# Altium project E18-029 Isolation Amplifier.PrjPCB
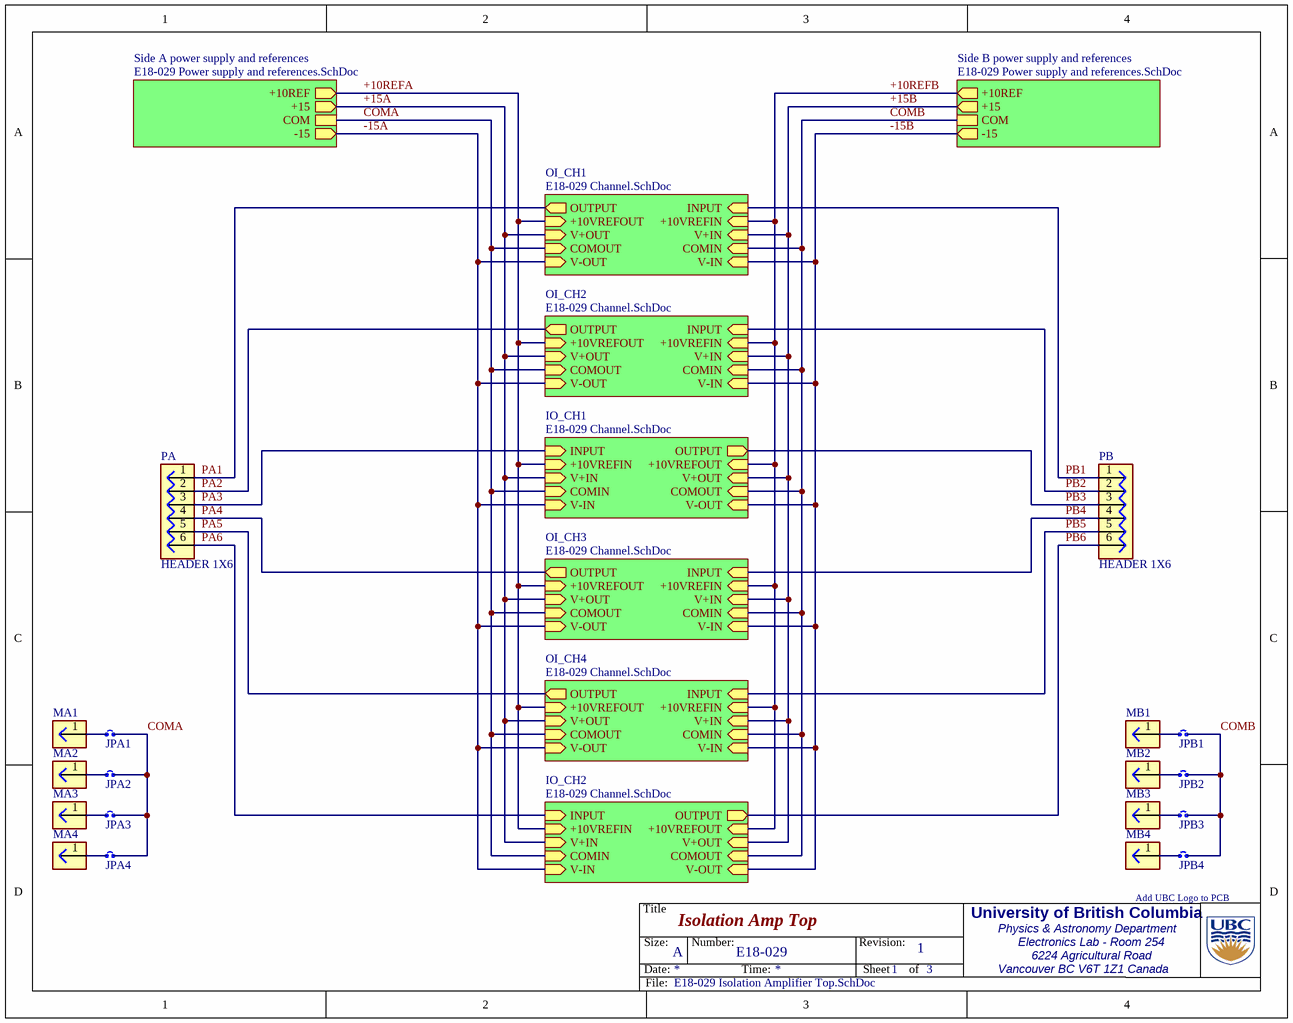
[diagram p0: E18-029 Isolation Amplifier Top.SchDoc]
3 sheets, 359 parts. Net scope: hierarchical (ports join the sheet entries above them; power ports are global).
Board file: E18-029 Isolation Amplifier.PcbDoc
Sheets:
  E18-029 Isolation Amplifier Top.SchDoc
    Side B power supply and references = E18-029 Power supply and references.SchDoc
    Side A power supply and references = E18-029 Power supply and references.SchDoc
    IO_CH1 = E18-029 Channel.SchDoc
    IO_CH2 = E18-029 Channel.SchDoc
    OI_CH1 = E18-029 Channel.SchDoc
    OI_CH2 = E18-029 Channel.SchDoc
    OI_CH3 = E18-029 Channel.SchDoc
    OI_CH4 = E18-029 Channel.SchDoc

## Sheet E18-029 Isolation Amplifier Top.SchDoc: Isolation Amp Top
size A; Author: MC; DrawnBy: M. Carlson; Organization: University of British Columbia; Address1: Physics & Astronomy Department; Address2: Electronics Lab - Room 254; Address3: 6224 Agricultural Road; Address4: Vancouver BC V6T 1Z1 Canada; DocumentNumber: E18-029; Revision: 1; SheetNumber: 1; SheetTotal: 3

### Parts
JPA1  JMPR  [Jumper 1210]  (value not drawn)
JPA2  JMPR  [Jumper 1210]  (value not drawn)
JPA3  JMPR  [Jumper 1210]  (value not drawn)
JPA4  JMPR  [Jumper 1210]  (value not drawn)
JPB1  JMPR  [Jumper 1210]  (value not drawn)
JPB2  JMPR  [Jumper 1210]  (value not drawn)
JPB3  JMPR  [Jumper 1210]  (value not drawn)
JPB4  JMPR  [Jumper 1210]  (value not drawn)
Logo?  Use UBC Logo  [UBC Logo]  (value not drawn)  (no BOM)
MA1  Pad  [Mtg_Hole_M4 no silk]  (value not drawn)
MA2  Pad  [Mtg_Hole_M4 no silk]  (value not drawn)
MA3  Pad  [Mtg_Hole_M4 no silk]  (value not drawn)
MA4  Pad  [Mtg_Hole_M4 no silk]  (value not drawn)
MB1  Pad  [Mtg_Hole_M4 no silk]  (value not drawn)
MB2  Pad  [Mtg_Hole_M4 no silk]  (value not drawn)
MB3  Pad  [Mtg_Hole_M4 no silk]  (value not drawn)
MB4  Pad  [Mtg_Hole_M4 no silk]  (value not drawn)
PA  HEADER 1X6  [HDR1X6 SMD]
PB  HEADER 1X6  [HDR1X6 SMD]

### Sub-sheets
IO_CH1 = E18-029 Channel.SchDoc: +10VREFIN (in), INPUT (in), +10VREFOUT (in), OUTPUT (out), V+IN (in), V-IN (in), COMIN (in), V+OUT (in), V-OUT (in), COMOUT (in)
IO_CH2 = E18-029 Channel.SchDoc: +10VREFIN (in), INPUT (in), +10VREFOUT (in), OUTPUT (out), V+IN (in), V-IN (in), COMIN (in), V+OUT (in), V-OUT (in), COMOUT (in)
OI_CH1 = E18-029 Channel.SchDoc: +10VREFIN (in), INPUT (in), +10VREFOUT (in), OUTPUT (out), V+IN (in), V-IN (in), COMIN (in), V+OUT (in), V-OUT (in), COMOUT (in)
OI_CH2 = E18-029 Channel.SchDoc: +10VREFIN (in), INPUT (in), +10VREFOUT (in), OUTPUT (out), V+IN (in), V-IN (in), COMIN (in), V+OUT (in), V-OUT (in), COMOUT (in)
OI_CH3 = E18-029 Channel.SchDoc: +10VREFIN (in), INPUT (in), +10VREFOUT (in), OUTPUT (out), V+IN (in), V-IN (in), COMIN (in), V+OUT (in), V-OUT (in), COMOUT (in)
OI_CH4 = E18-029 Channel.SchDoc: +10VREFIN (in), INPUT (in), +10VREFOUT (in), OUTPUT (out), V+IN (in), V-IN (in), COMIN (in), V+OUT (in), V-OUT (in), COMOUT (in)
Side A power supply and references = E18-029 Power supply and references.SchDoc: +15 (out), COM, -15 (out), +10REF (out)
Side B power supply and references = E18-029 Power supply and references.SchDoc: +15 (out), COM, -15 (out), +10REF (out)

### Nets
+15A: sheet Side B power supply and references/+15, sheet Side A power supply and references/+15, sheet IO_CH1/V+IN, sheet IO_CH1/V+OUT, sheet IO_CH2/V+IN, sheet IO_CH2/V+OUT, sheet OI_CH1/V+IN, sheet OI_CH1/V+OUT, sheet OI_CH2/V+IN, sheet OI_CH2/V+OUT, sheet OI_CH3/V+IN, sheet OI_CH3/V+OUT, sheet OI_CH4/V+IN, sheet OI_CH4/V+OUT  [also labelled +15B]
-15A: sheet Side B power supply and references/-15, sheet Side A power supply and references/-15, sheet IO_CH1/V-IN, sheet IO_CH1/V-OUT, sheet IO_CH2/V-IN, sheet IO_CH2/V-OUT, sheet OI_CH1/V-IN, sheet OI_CH1/V-OUT, sheet OI_CH2/V-IN, sheet OI_CH2/V-OUT, sheet OI_CH3/V-IN, sheet OI_CH3/V-OUT, sheet OI_CH4/V-IN, sheet OI_CH4/V-OUT  [also labelled -15B]
COMA: JPA1.2 JPA2.2 JPA3.2 JPA4.2 JPB1.2 JPB2.2 JPB3.2 JPB4.2 ; sheet Side B power supply and references/COM, sheet Side A power supply and references/COM, sheet IO_CH1/COMIN, sheet IO_CH1/COMOUT, sheet IO_CH2/COMIN, sheet IO_CH2/COMOUT, sheet OI_CH1/COMIN, sheet OI_CH1/COMOUT, sheet OI_CH2/COMIN, sheet OI_CH2/COMOUT, sheet OI_CH3/COMIN, sheet OI_CH3/COMOUT, sheet OI_CH4/COMIN, sheet OI_CH4/COMOUT  [also labelled COMB]
+10REFA: sheet Side A power supply and references/+10REF, sheet IO_CH1/+10VREFIN, sheet IO_CH2/+10VREFIN, sheet OI_CH1/+10VREFOUT, sheet OI_CH2/+10VREFOUT, sheet OI_CH3/+10VREFOUT, sheet OI_CH4/+10VREFOUT
+10REFB: sheet Side B power supply and references/+10REF, sheet IO_CH1/+10VREFOUT, sheet IO_CH2/+10VREFOUT, sheet OI_CH1/+10VREFIN, sheet OI_CH2/+10VREFIN, sheet OI_CH3/+10VREFIN, sheet OI_CH4/+10VREFIN
PA1: PA.1 ; sheet OI_CH1/OUTPUT
PA2: PA.2 ; sheet OI_CH2/OUTPUT
PA3: PA.3 ; sheet IO_CH1/INPUT
PA4: PA.4 ; sheet OI_CH3/OUTPUT
PA5: PA.5 ; sheet OI_CH4/OUTPUT
PA6: PA.6 ; sheet IO_CH2/INPUT
PB1: PB.1 ; sheet OI_CH1/INPUT
PB2: PB.2 ; sheet OI_CH2/INPUT
PB3: PB.3 ; sheet IO_CH1/OUTPUT
PB4: PB.4 ; sheet OI_CH3/INPUT
PB5: PB.5 ; sheet OI_CH4/INPUT
PB6: PB.6 ; sheet IO_CH2/OUTPUT
NetJPA1_1: JPA1.1 MA1.1
NetJPA2_1: JPA2.1 MA2.1
NetJPA3_1: JPA3.1 MA3.1
NetJPA4_1: JPA4.1 MA4.1
NetJPB1_1: JPB1.1 MB1.1
NetJPB2_1: JPB2.1 MB2.1
NetJPB3_1: JPB3.1 MB3.1
NetJPB4_1: JPB4.1 MB4.1

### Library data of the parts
JPA1-JPA4 JPB1-JPB4 = Jumper2P_SMD: 2 Pin Jumper Solder Pads; Manufacturer: Generic Components; Class: Passive
Logo? = Directive: Add UBC Logo to PCB: UBC Logo
MA1-MA4 MB1-MB4 = Mounting Pad: Manufacturer: AMP; Part No.: PAD_HV
PA PB = HEADER 1X6: 0.1" Spacing 1x6 Header; Manufacturer: AMP

## Sheet E18-029 Power supply and references.SchDoc: Power Supply and Reference
size A; DrawnBy: M. Carlson; Organization: University of British Columbia; Address1: Physics & Astronomy Department; Address2: Electronics Lab - Room 254; Address3: 6224 Agricultural Road; Address4: Vancouver BC V6T 1Z1 Canada; DocumentNumber: E18-029; Revision: 1; SheetNumber: 2; SheetTotal: 3
Used 2 times, as channels Side B power supply and references, Side A power supply and references. Parts and nets are listed once, with the designators drawn on the sheet.
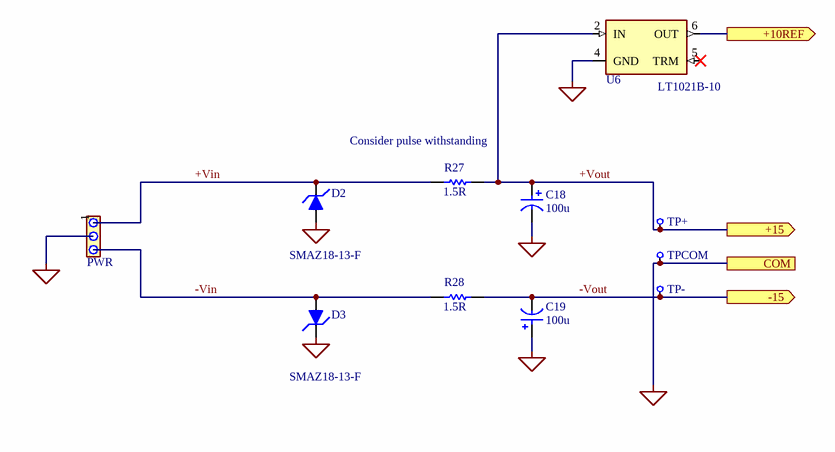
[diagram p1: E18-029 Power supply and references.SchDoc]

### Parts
C18  value 100u  [CC7343]  (hidden comment: CAP TANT POLY 100UF 25V 2917)
C19  value 100u  [CC7343]  (hidden comment: CAP TANT POLY 100UF 25V 2917)
D2  SMAZ18-13-F  [SMAJ]
D3  SMAZ18-13-F  [SMAJ]
PWR  JMPR  [HDR1X3 SMD]  (value not drawn)
R27  1.5R  [R1206]
R28  1.5R  [R1206]
TP+  Vero Eyelet Test Point  [TEST PT SMD]  (value not drawn)
TP-  Vero Eyelet Test Point  [TEST PT SMD]  (value not drawn)
TPCOM  Vero Eyelet Test Point  [PAD-110-52]  (value not drawn)
U6  LT1021B-10  [SO-G8]

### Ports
+10REF (out), +15 (out), -15 (out), COM

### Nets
GND: C18.2 C19.1 D2.1(A) D3.2(K) PWR.2 TPCOM.1 U6.4(GND) ; port COM
+10REF: U6.6(OUT) ; port +10REF
+Vin: D2.2(K) PWR.1 R27.2
+Vout: C18.1 R27.1 TP+.1 U6.2(IN) ; port +15
-Vin: D3.1(A) PWR.3 R28.2
-Vout: C19.2 R28.1 TP-.1 ; port -15

Not connected (* = marked no-connect by the designer): U6 5(TRM)*

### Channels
Side B power supply and references: designators end in _Side_B_power_supply_and_references; ports +10REF=+10REFB +15=+15A -15=-15A COM=COMA
Side A power supply and references: designators end in _Side_A_power_supply_and_references; ports +10REF=+10REFA +15=+15A -15=-15A COM=COMA

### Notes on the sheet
- Consider pulse withstanding

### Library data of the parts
C18 C19 = Cap Tant 100uF 10V: Manufacturer: AVX; Part Number: TCJE107M025R0080; Class: Passive; SubClass: Capacitor; Type: SMD; Scuba2 No.: 000523 CAP
D2 D3 = SMAZ18-13-F: Zener, 18V 1W SMAJ; Part Number: SMAZ15-13-F; Manufacturer: MCC; Class: Discrete; Subclass: Zener Diode; Type: SMT
PWR = Jumper3p: 3 Pin Jumper Header; Manufacturer: Generic Components; Class: Passive
R27 R28 = Res1: Resistor
TP+ TP- TPCOM = TP- Eyelet Terminal: Eyelet Test Point (white); Part Number: 20-313143A; Class: Passive
U6 = LT1021B-10: 2ppm/°C, Low-Noise, +10V Voltage Reference; Manufacturer: Maxim; Part Number: MAX6325CSA; Class: Power Management

## Sheet E18-029 Channel.SchDoc: Analog Channel
size A; Author: Mark Carlson; Organization: University of British Columbia; Address1: Physics & Astronomy Department; Address2: Electronics Lab - Room 254; Address3: 6224 Agricultural Road; Address4: Vancouver BC V6T 1Z1 Canada; DocumentNumber: E18-029; Revision: 1; SheetNumber: 3; SheetTotal: 3
Used 6 times, as channels IO_CH1, IO_CH2, OI_CH1, OI_CH2, OI_CH3, OI_CH4. Parts and nets are listed once, with the designators drawn on the sheet.
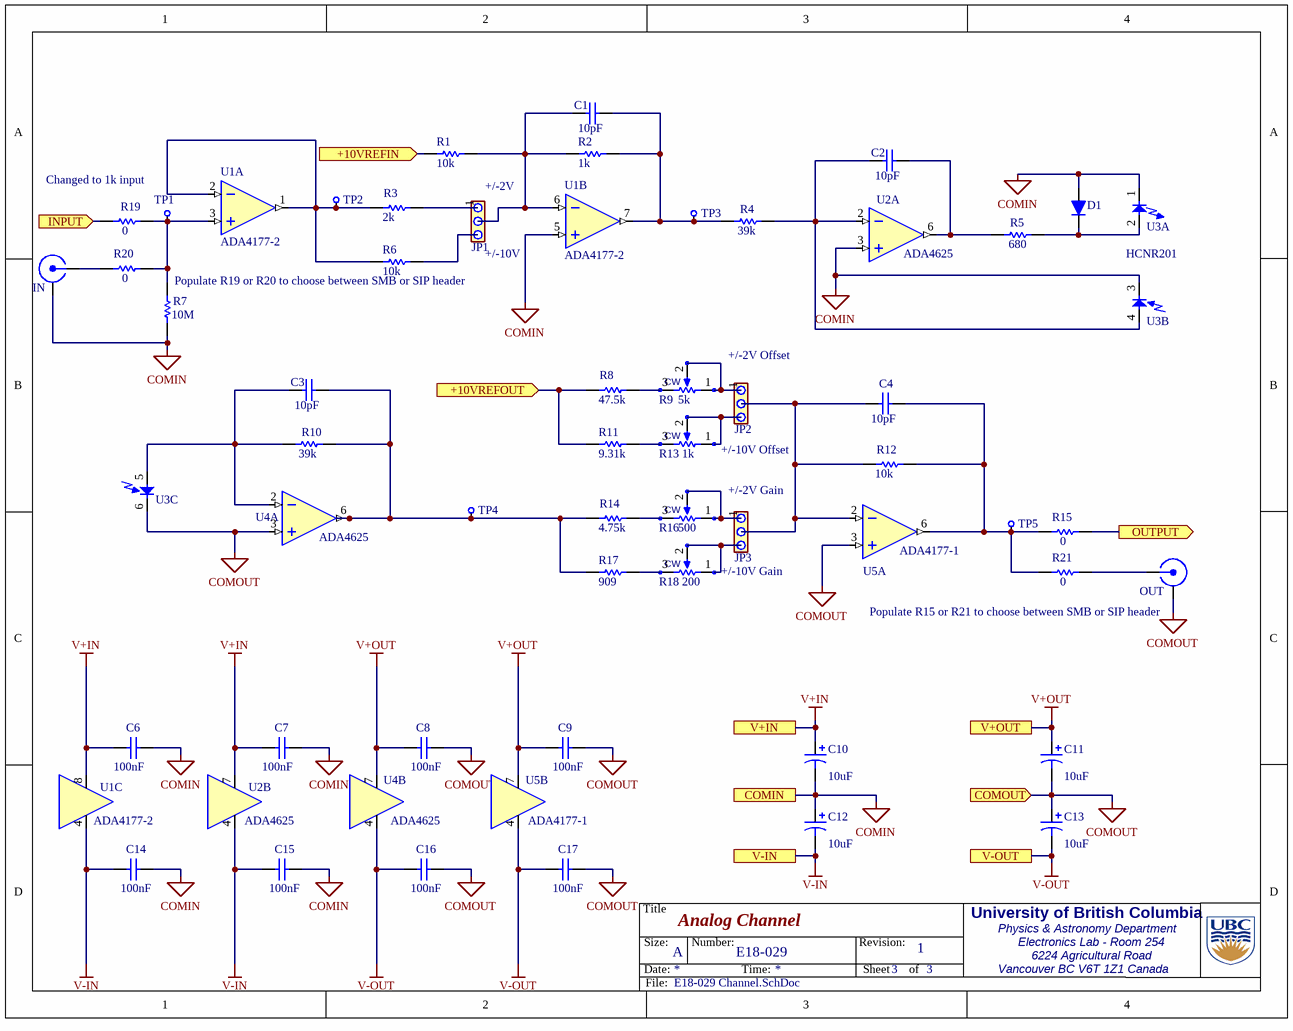
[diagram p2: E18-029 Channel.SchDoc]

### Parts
C1  10pF  [6-0805_M]
C2  10pF  [6-0805_M]
C3  10pF  [6-0805_M]
C4  10pF  [6-0805_M]
C6  100nF  [6-0805_M]
C7  100nF  [6-0805_M]
C8  100nF  [6-0805_M]
C9  100nF  [6-0805_M]
C10  value 10uF  [CC3216]  (hidden comment: Tant Poly 10uF)
C11  value 10uF  [CC3216]  (hidden comment: Tant Poly 10uF)
C12  value 10uF  [CC3216]  (hidden comment: Tant Poly 10uF)
C13  value 10uF  [CC3216]  (hidden comment: Tant Poly 10uF)
C14  100nF  [6-0805_M]
C15  100nF  [6-0805_M]
C16  100nF  [6-0805_M]
C17  100nF  [6-0805_M]
D1  1N4148W  [SOD-123]  (value not drawn)
IN  SMB Male Vertical Mount  [SMB_Male_Vertical]  (value not drawn)
JP1  JMPR  [HDR1X3 SMD]  (value not drawn)
JP2  JMPR  [HDR1X3 SMD]  (value not drawn)
JP3  JMPR  [HDR1X3 SMD]  (value not drawn)
OUT  SMB Male Vertical Mount  [SMB_Male_Vertical]  (value not drawn)
R1  10k  [6-0805_M]
R2  1k  [6-0805_M]
R3  2k  [6-0805_M]
R4  39k  [R1206]
R5  680  [6-0805_M]
R6  10k  [6-0805_M]
R7  10M  [6-0805_M]
R8  47.5k  [6-0805_M]
R9  value 5k  End: CW  [POT SMD]  (hidden comment: RPot8)
R10  39k  [6-0805_M]
R11  9.31k  [6-0805_M]
R12  10k  [6-0805_M]
R13  value 1k  End: CW  [POT SMD]  (hidden comment: RPot8)
R14  4.75k  [6-0805_M]
R15  0  [6-0805_M]
R16  value 500  End: CW  [POT SMD]  (hidden comment: RPot8)
R17  909  [6-0805_M]
R18  value 200  End: CW  [POT SMD]  (hidden comment: RPot8)
R19  0  [6-0805_M]
R20  value 0  [6-0805_M]  (hidden comment: 2.2k)
R21  0  [6-0805_M]
TP1  Vero Eyelet Test Point  [TEST PT SMD]  (value not drawn)
TP2  Vero Eyelet Test Point  [TEST PT SMD]  (value not drawn)
TP3  Vero Eyelet Test Point  [TEST PT SMD]  (value not drawn)
TP4  Vero Eyelet Test Point  [TEST PT SMD]  (value not drawn)
TP5  Vero Eyelet Test Point  [TEST PT SMD]  (value not drawn)
U1  ADA4177-2  [SO-G8]  (parts A,B,C of 3)
U2  ADA4625  [SO-G8]  (parts A,B of 2)
U3  HCNR201  [DIP-8GW]  (parts A,B,C of 3)
U4  ADA4625  [SO-G8]  (parts A,B of 2)
U5  ADA4177-1  [SO-G8]  (parts A,B of 2)

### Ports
+10VREFIN (in), +10VREFOUT (in), COMIN, COMOUT (in), INPUT (in), OUTPUT (out), V+IN, V+OUT, V-IN, V-OUT

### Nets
COMIN: C6.1 C7.1 C10.2 C12.1 C14.1 C15.1 D1.1(A) IN.2 R7.1 U1.5(IN+2) U2.3(IN+) U3.1(LED_K) U3.3(PD1-K) ; port COMIN
COMOUT: C8.1 C9.1 C11.2 C13.1 C16.1 C17.1 OUT.2 U3.6(PD2-K) U4.3(IN+) U5.3(IN+) ; port COMOUT
V+IN: C6.2 C7.2 C10.1 U1.8(V+) U2.7(+Vs) ; port V+IN
V+OUT: C8.2 C9.2 C11.1 U4.7(+Vs) U5.7(+Vs) ; port V+OUT
V-IN: C12.2 C14.2 C15.2 U1.4(V-) U2.4(-Vs) ; port V-IN
V-OUT: C13.2 C16.2 C17.2 U4.4(-Vs) U5.4(-Vs) ; port V-OUT
+10VREFIN: R1.2 ; port +10VREFIN
+10VREFOUT: R8.2 R11.2 ; port +10VREFOUT
INPUT: R19.2 ; port INPUT
OUTPUT: R15.1 ; port OUTPUT
NetC1_1: C1.1 R2.1 R4.1 TP3.1 U1.7(OUT2)
NetC1_2: C1.2 JP1.2 R1.1 R2.2 U1.6(IN-2)
NetC2_1: C2.1 R5.1 U2.6(OUT)
NetC2_2: C2.2 R4.2 U2.2(IN-) U3.4(PD1-A)
NetC3_1: C3.1 R10.2 R14.2 R17.2 TP4.1 U4.6(OUT)
NetC3_2: C3.2 R10.1 U3.5(PD2-A) U4.2(IN-)
NetC4_1: C4.1 R12.1 R15.2 R21.2 TP5.1 U5.6(OUT)
NetC4_2: C4.2 JP2.2 JP3.2 R12.2 U5.2(IN-)
NetD1_2: D1.2(K) R5.2 U3.2(LED_A)
NetIN_1: IN.1 R20.2
NetJP1_1: JP1.1 R3.1
NetJP1_3: JP1.3 R6.1
NetJP2_1: JP2.1 R9.1 R9.2
NetJP2_3: JP2.3 R13.1 R13.2
NetJP3_1: JP3.1 R16.1 R16.2
NetJP3_3: JP3.3 R18.1 R18.2
NetOUT_1: OUT.1 R21.1
NetR3_2: R3.2 R6.2 TP2.1 U1.1(OUT1) U1.2(IN-1)
NetR7_2: R7.2 R19.1 R20.1 TP1.1 U1.3(IN+1)
NetR8_1: R8.1 R9.3
NetR11_1: R11.1 R13.3
NetR14_1: R14.1 R16.3
NetR17_1: R17.1 R18.3

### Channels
IO_CH1: designators end in _IO_CH1; ports +10VREFIN=+10REFA +10VREFOUT=+10REFB COMIN=COMA COMOUT=COMA INPUT=PA3 OUTPUT=PB3 V+IN=+15A V+OUT=+15A V-IN=-15A V-OUT=-15A
IO_CH2: designators end in _IO_CH2; ports +10VREFIN=+10REFA +10VREFOUT=+10REFB COMIN=COMA COMOUT=COMA INPUT=PA6 OUTPUT=PB6 V+IN=+15A V+OUT=+15A V-IN=-15A V-OUT=-15A
OI_CH1: designators end in _OI_CH1; ports +10VREFIN=+10REFB +10VREFOUT=+10REFA COMIN=COMA COMOUT=COMA INPUT=PB1 OUTPUT=PA1 V+IN=+15A V+OUT=+15A V-IN=-15A V-OUT=-15A
OI_CH2: designators end in _OI_CH2; ports +10VREFIN=+10REFB +10VREFOUT=+10REFA COMIN=COMA COMOUT=COMA INPUT=PB2 OUTPUT=PA2 V+IN=+15A V+OUT=+15A V-IN=-15A V-OUT=-15A
OI_CH3: designators end in _OI_CH3; ports +10VREFIN=+10REFB +10VREFOUT=+10REFA COMIN=COMA COMOUT=COMA INPUT=PB4 OUTPUT=PA4 V+IN=+15A V+OUT=+15A V-IN=-15A V-OUT=-15A
OI_CH4: designators end in _OI_CH4; ports +10VREFIN=+10REFB +10VREFOUT=+10REFA COMIN=COMA COMOUT=COMA INPUT=PB5 OUTPUT=PA5 V+IN=+15A V+OUT=+15A V-IN=-15A V-OUT=-15A

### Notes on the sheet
- Changed to 1k input
- (near JP1) +/-2V
- Populate R19 or R20 to choose between SMB or SIP header
- (near JP1) +/-10V
- +/-2V Offset
- +/-10V Offset
- +/-2V Gain
- +/-10V Gain
- Populate R15 or R21 to choose between SMB or SIP header

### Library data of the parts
C1-C4 C6-C9 C14-C17 = Cap: Capacitor
C10-C13 = Cap Pol3: CAP TANT POLY 10UF 25V 1206
D1 = 1N4148W: High Conductance Fast Diode; Manufacturer: Fairchild Semiconductor; Revised: 11-July-2000: SIM Model Added.; Class: Discrete; SubClass: Diode - Switching; Type: SMD
IN OUT = SMB_Male_Vertical: SMA Male Vertical Mount; Manufacturer: Amphenol; Class: Connector; Fitted: POP
JP1-JP3 = Jumper3p: as PWR on sheet E18-029 Power supply and references
R1-R8 R10-R12 R14 R15 R17 R19-R21 = Res1: Resistor
R9 R13 R16 R18 = RPot8: SMD POT; Manufacturer: Vishay; Part Number: TS63Y; Class: Passive; SubClass: Potentiometer
TP1-TP5 = TP- Eyelet Terminal: as TP+ on sheet E18-029 Power supply and references
U1 = ADA4177-2: OVP and EMI Protected, Precision, / Low Noise and Bias Current Dual Op Amp; Manufacturer: Analog Devices; Class: Analog; SubClass: Operational Amp
U2 = ADA4625: 36V, 18MHz, Low Noise, JFET Op Amp; Manufacturer: Analog Devices; Class: Amplifier; SubClass: Operational Amplifier
U3 = HCNR201: Analog Optocoupler; Manufacturer: Agilent; Class: Electrical Isolation; SubClass: Opto-coupler
U4 = ADA4625: 36V, 18MHz, Low Noise, JFET Op Amp; Manufacturer: Analog Devices; Part Number: AD548KR; Class: Amplifier; SubClass: Operational Amplifier
U5 = ADA4177-1: OVP and EMI Protected, Precision, / Low Noise and Bias Current Dual Op Amp; Manufacturer: Analog Devices; Class: Amplifier; SubClass: Operational Amplifier

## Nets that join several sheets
+15A: Side B power supply and references (C18_Side_B_power_supply_and_references.1 R27_Side_B_power_supply_and_references.1 TP+_Side_B_power_supply_and_references.1 U6_Side_B_power_supply_and_references.2), Side A power supply and references (C18_Side_A_power_supply_and_references.1 R27_Side_A_power_supply_and_references.1 TP+_Side_A_power_supply_and_references.1 U6_Side_A_power_supply_and_references.2), IO_CH1 (10 pins), IO_CH2 (10 pins), OI_CH1 (10 pins), OI_CH2 (10 pins), OI_CH3 (10 pins), OI_CH4 (10 pins)
-15A: Side B power supply and references (C19_Side_B_power_supply_and_references.2 R28_Side_B_power_supply_and_references.1 TP-_Side_B_power_supply_and_references.1), Side A power supply and references (C19_Side_A_power_supply_and_references.2 R28_Side_A_power_supply_and_references.1 TP-_Side_A_power_supply_and_references.1), IO_CH1 (10 pins), IO_CH2 (10 pins), OI_CH1 (10 pins), OI_CH2 (10 pins), OI_CH3 (10 pins), OI_CH4 (10 pins)
COMA: E18-029 Isolation Amplifier Top (8 pins), Side B power supply and references (7 pins), Side A power supply and references (7 pins), IO_CH1 (23 pins), IO_CH2 (23 pins), OI_CH1 (23 pins), OI_CH2 (23 pins), OI_CH3 (23 pins), OI_CH4 (23 pins)
+10REFA: Side A power supply and references (U6_Side_A_power_supply_and_references.6), IO_CH1 (R1_IO_CH1.2), IO_CH2 (R1_IO_CH2.2), OI_CH1 (R8_OI_CH1.2 R11_OI_CH1.2), OI_CH2 (R8_OI_CH2.2 R11_OI_CH2.2), OI_CH3 (R8_OI_CH3.2 R11_OI_CH3.2), OI_CH4 (R8_OI_CH4.2 R11_OI_CH4.2)
+10REFB: Side B power supply and references (U6_Side_B_power_supply_and_references.6), IO_CH1 (R8_IO_CH1.2 R11_IO_CH1.2), IO_CH2 (R8_IO_CH2.2 R11_IO_CH2.2), OI_CH1 (R1_OI_CH1.2), OI_CH2 (R1_OI_CH2.2), OI_CH3 (R1_OI_CH3.2), OI_CH4 (R1_OI_CH4.2)
PA1: E18-029 Isolation Amplifier Top (PA.1), OI_CH1 (R15_OI_CH1.1)
PA2: E18-029 Isolation Amplifier Top (PA.2), OI_CH2 (R15_OI_CH2.1)
PA3: E18-029 Isolation Amplifier Top (PA.3), IO_CH1 (R19_IO_CH1.2)
PA4: E18-029 Isolation Amplifier Top (PA.4), OI_CH3 (R15_OI_CH3.1)
PA5: E18-029 Isolation Amplifier Top (PA.5), OI_CH4 (R15_OI_CH4.1)
PA6: E18-029 Isolation Amplifier Top (PA.6), IO_CH2 (R19_IO_CH2.2)
PB1: E18-029 Isolation Amplifier Top (PB.1), OI_CH1 (R19_OI_CH1.2)
PB2: E18-029 Isolation Amplifier Top (PB.2), OI_CH2 (R19_OI_CH2.2)
PB3: E18-029 Isolation Amplifier Top (PB.3), IO_CH1 (R15_IO_CH1.1)
PB4: E18-029 Isolation Amplifier Top (PB.4), OI_CH3 (R19_OI_CH3.2)
PB5: E18-029 Isolation Amplifier Top (PB.5), OI_CH4 (R19_OI_CH4.2)
PB6: E18-029 Isolation Amplifier Top (PB.6), IO_CH2 (R15_IO_CH2.1)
